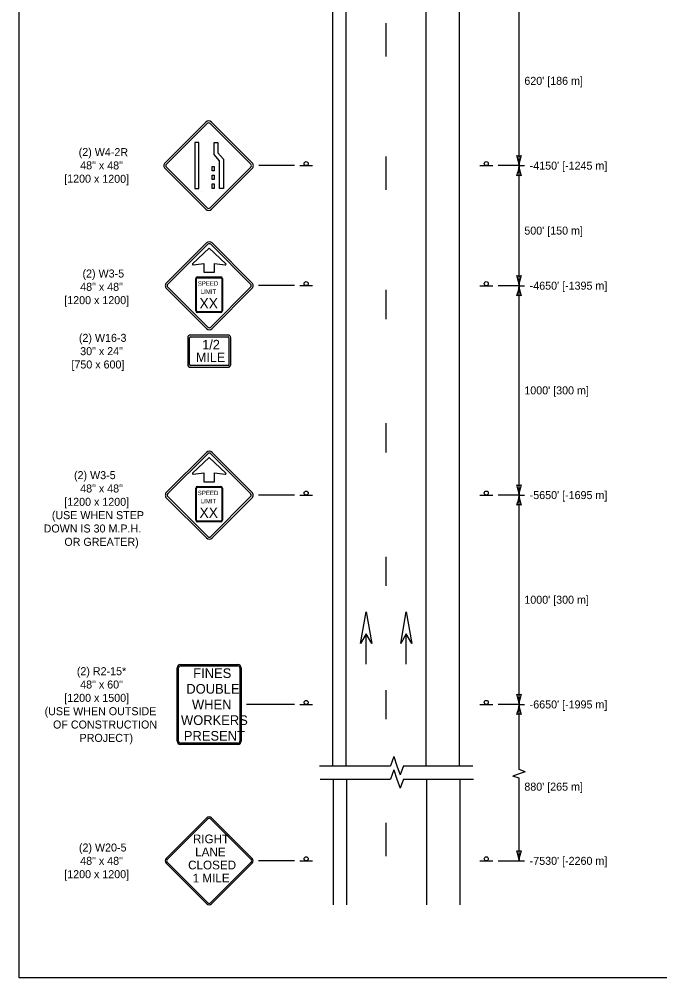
# Model space of a CAD drawing. Extents: x 49991.4 to 50021, y 49987.6 to 50011.4.
# Drawn here: x 49999.38 to 50004.19, y 49987.8 to 49994.99 of the extents above; entities that cross this region are included whole.
import ezdxf

# ---------------------------------------------------------------- set-up
doc = ezdxf.new("R2010")
doc.units = 0
for name, color, linetype in [('Level 1', 7, 'Continuous'), ('Level 2', 7, 'Continuous'), ('Level 25', 7, 'Continuous'), ('Level 3', 7, 'Continuous'), ('Level 6', 7, 'Continuous')]:
    doc.layers.add(name, color=color, linetype=linetype)

msp = doc.modelspace()

# ---------------------------------------------------------------- linework, layer by layer
at = {"layer": 'Level 1'}
for p, q in [((50001.7353, 49989.3888), (50001.7353, 49998.1941)), ((50001.8353, 49989.3888), (50001.8353, 49998.1941)), ((50002.4353, 49989.3888), (50002.4353, 49998.1941)), ((50002.6853, 49989.3888), (50002.6853, 49998.1941)), ((50002.1353, 49994.7064), (50002.1353, 49994.9564)), ((50002.1353, 49993.7064), (50002.1353, 49993.9564)), ((50001.4873, 49993.8881), (50001.5833, 49993.8881)), ((50002.8373, 49993.8882), (50002.9333, 49993.8882)), ((50000.7869, 49993.3085), (50000.4876, 49993.0092)), ((50000.797, 49993.2984), (50000.4977, 49992.9991)), ((50000.8082, 49993.27), (50000.6838, 49993.1527)), ((50000.7869, 49993.3085), (50000.7869, 49993.3085)), ((50000.797, 49993.2984), (50000.797, 49993.2984)), ((50000.9327, 49993.1527), (50000.8082, 49993.27)), ((50001.1188, 49992.9991), (50000.8195, 49993.2984)), ((50001.1289, 49993.0092), (50000.8296, 49993.3085)), ((50000.6879, 49993.1441), (50000.7679, 49993.1541)), ((50000.7679, 49993.1541), (50000.7679, 49993.0886)), ((50000.8486, 49993.0886), (50000.8486, 49993.1541)), ((50000.8486, 49993.1541), (50000.9286, 49993.1441)), ((50000.7204, 49993.0535), (50000.8951, 49993.0535)), ((50000.7204, 49993.0483), (50000.8951, 49993.0483)), ((50000.7679, 49993.0886), (50000.8486, 49993.0886)), ((50000.8077, 49993.0535), (50000.8077, 49993.0535)), ((50000.4977, 49992.9765), (50000.797, 49992.6772)), ((50000.7079, 49992.7997), (50000.7079, 49993.041)), ((50000.7131, 49992.7997), (50000.7131, 49993.041)), ((50000.8195, 49992.6772), (50001.1188, 49992.9765)), ((50000.9024, 49993.041), (50000.9024, 49992.7997)), ((50000.9076, 49993.041), (50000.9076, 49992.7997)), ((50001.4873, 49992.9886), (50001.5833, 49992.9886)), ((50002.8373, 49992.9882), (50002.9333, 49992.9882)), ((50000.4876, 49992.9664), (50000.7869, 49992.6671)), ((50000.8296, 49992.6671), (50001.1289, 49992.9664)), ((50002.1353, 49992.7372), (50002.1353, 49992.9564)), ((50000.8951, 49992.7924), (50000.7204, 49992.7924)), ((50000.8951, 49992.7873), (50000.7204, 49992.7873)), ((50000.9494, 49992.6182), (50000.6671, 49992.6182)), ((50000.647, 49992.5981), (50000.647, 49992.3965)), ((50000.6604, 49992.3965), (50000.6604, 49992.5981)), ((50000.6671, 49992.6048), (50000.9494, 49992.6048)), ((50000.9561, 49992.5981), (50000.9561, 49992.3965)), ((50000.9695, 49992.3965), (50000.9695, 49992.5981)), ((50000.9494, 49992.3898), (50000.6671, 49992.3898)), ((50000.6671, 49992.3763), (50000.9494, 49992.3763)), ((50002.1353, 49991.7372), (50002.1353, 49991.9564)), ((50000.7869, 49991.7384), (50000.4876, 49991.4391)), ((50000.797, 49991.7283), (50000.4977, 49991.429)), ((50000.8082, 49991.6999), (50000.6838, 49991.5826)), ((50000.7869, 49991.7384), (50000.7869, 49991.7384)), ((50000.797, 49991.7283), (50000.797, 49991.7283)), ((50000.9327, 49991.5826), (50000.8082, 49991.6999)), ((50001.1188, 49991.429), (50000.8195, 49991.7283)), ((50001.1289, 49991.4391), (50000.8296, 49991.7384)), ((50000.6879, 49991.574), (50000.7679, 49991.584)), ((50000.7679, 49991.584), (50000.7679, 49991.5185)), ((50000.8486, 49991.5185), (50000.8486, 49991.584)), ((50000.8486, 49991.584), (50000.9286, 49991.574)), ((50000.7079, 49991.2296), (50000.7079, 49991.4709)), ((50000.7131, 49991.2296), (50000.7131, 49991.4709)), ((50000.7204, 49991.4834), (50000.8951, 49991.4834)), ((50000.7204, 49991.4782), (50000.8951, 49991.4782)), ((50000.7679, 49991.5185), (50000.8486, 49991.5185)), ((50000.8077, 49991.4834), (50000.8077, 49991.4834)), ((50000.9024, 49991.4709), (50000.9024, 49991.2296)), ((50000.9076, 49991.4709), (50000.9076, 49991.2296)), ((50000.4876, 49991.3963), (50000.7869, 49991.097)), ((50000.4977, 49991.4064), (50000.797, 49991.1071)), ((50000.8195, 49991.1071), (50001.1188, 49991.4064)), ((50000.8296, 49991.097), (50001.1289, 49991.3963)), ((50001.4873, 49991.4178), (50001.5833, 49991.4178)), ((50002.8373, 49991.4184), (50002.9333, 49991.4184)), ((50000.8951, 49991.2223), (50000.7204, 49991.2223)), ((50000.8951, 49991.2172), (50000.7204, 49991.2172)), ((50002.1353, 49990.7372), (50002.1353, 49990.9564)), ((50001.9853, 49990.1516), (50001.9853, 49990.3776)), ((50001.9856, 49990.1516), (50001.9856, 49990.3776)), ((50002.2853, 49990.1516), (50002.2853, 49990.3776)), ((50002.2856, 49990.1516), (50002.2856, 49990.3776)), ((50000.5682, 49989.5729), (50000.5682, 49990.1229)), ((50000.5782, 49989.5729), (50000.5782, 49990.1229)), ((50000.5932, 49990.1479), (50001.0232, 49990.1479)), ((50000.5932, 49990.1379), (50001.0232, 49990.1379)), ((50001.0382, 49990.1229), (50001.0382, 49989.5729)), ((50001.0482, 49990.1229), (50001.0482, 49989.5729)), ((50002.1353, 49989.7372), (50002.1353, 49989.9564)), ((50001.4873, 49989.8479), (50001.5833, 49989.8479)), ((50002.8373, 49989.8486), (50002.9333, 49989.8486)), ((50001.0232, 49989.5579), (50000.5932, 49989.5579)), ((50001.0232, 49989.5479), (50000.5932, 49989.5479)), ((50001.7405, 49988.3469), (50001.7405, 49989.2888)), ((50001.8405, 49988.3469), (50001.8405, 49989.2888)), ((50002.4405, 49988.3469), (50002.4405, 49989.2888)), ((50002.6905, 49988.3469), (50002.6905, 49989.2888)), ((50000.4865, 49988.6936), (50000.7906, 49988.9976)), ((50000.4936, 49988.6865), (50000.7976, 49988.9906)), ((50000.8189, 49988.9906), (50001.1229, 49988.6865)), ((50000.8259, 49988.9976), (50001.13, 49988.6936)), ((50002.1353, 49988.711), (50002.1353, 49988.961)), ((50000.7976, 49988.3612), (50000.4936, 49988.6653)), ((50001.1229, 49988.6653), (50000.8189, 49988.3612)), ((50001.4873, 49988.6756), (50001.5833, 49988.6756)), ((50002.8373, 49988.6759), (50002.9333, 49988.6759)), ((50000.7906, 49988.3542), (50000.4865, 49988.6582)), ((50001.13, 49988.6582), (50000.8259, 49988.3542))]:
    msp.add_line(p, q, dxfattribs=at)
for points in [[(49999.3835, 49998.9992), (50016.7501, 49998.9992), (50016.7501, 49987.7988), (49999.3835, 49987.7988)], [(50001.9436, 49990.3052), (50001.9853, 49990.5418), (50002.0272, 49990.3052), (50001.9853, 49990.3774)], [(50002.2436, 49990.3052), (50002.2853, 49990.5418), (50002.3272, 49990.3052), (50002.2853, 49990.3774)]]:
    msp.add_lwpolyline(points, close=True, dxfattribs=at)
for centre in [(50001.5353, 49993.9033), (50002.8853, 49993.9034), (50001.5353, 49993.0038), (50002.8853, 49993.0034), (50001.5353, 49991.433), (50002.8853, 49991.4336), (50001.5353, 49989.8631), (50002.8853, 49989.8638), (50001.5353, 49988.6908), (50002.8853, 49988.6912)]:
    msp.add_circle(centre, 0.0152, dxfattribs=at)
for centre, radius, start, end in [((50000.8082, 49993.2871), 0.0302, 45.00007, 134.99993), ((50000.8082, 49993.2871), 0.016, 45.00007, 134.99993), ((50000.6874, 49993.1491), 0.00508, 134.62874, 275.82948), ((50000.9291, 49993.1491), 0.00509, 264.38259, 45.16491), ((50000.7204, 49993.041), 0.0125, 90, 180), ((50000.7204, 49993.041), 0.00728, 90, 180), ((50000.8951, 49993.041), 0.0125, 360, 90), ((50000.8951, 49993.041), 0.00728, 360, 90), ((50000.5089, 49992.9878), 0.0302, 134.99993, 225.00008), ((50000.5089, 49992.9878), 0.016, 134.99993, 225.00008), ((50001.1075, 49992.9878), 0.016, 314.99993, 45.00007), ((50001.1075, 49992.9878), 0.0302, 314.99993, 45.00008), ((50000.7204, 49992.7997), 0.0125, 180, 270), ((50000.7204, 49992.7997), 0.00728, 180, 270), ((50000.8951, 49992.7997), 0.00728, 270, 360), ((50000.8951, 49992.7997), 0.0125, 270, 360), ((50000.6671, 49992.5981), 0.0202, 90, 180), ((50000.8082, 49992.6885), 0.0302, 225.00007, 314.99993), ((50000.8082, 49992.6885), 0.016, 225.00007, 314.99993), ((50000.9494, 49992.5981), 0.0202, 0, 90), ((50000.6671, 49992.5981), 0.00672, 90, 180), ((50000.9494, 49992.5981), 0.00672, 0, 90), ((50000.6671, 49992.3965), 0.0202, 180, 270), ((50000.6671, 49992.3965), 0.00672, 180, 270), ((50000.9494, 49992.3965), 0.00672, 270, 0), ((50000.9494, 49992.3965), 0.0202, 270, 0), ((50000.8082, 49991.717), 0.0302, 45.00007, 134.99993), ((50000.8082, 49991.717), 0.016, 45.00007, 134.99993), ((50000.6874, 49991.579), 0.00508, 134.62874, 275.82948), ((50000.9291, 49991.579), 0.00509, 264.38259, 45.16491), ((50000.7204, 49991.4709), 0.0125, 90, 180), ((50000.7204, 49991.4709), 0.00728, 90, 180), ((50000.8951, 49991.4709), 0.0125, 360, 90), ((50000.8951, 49991.4709), 0.00728, 360, 90), ((50000.5089, 49991.4177), 0.0302, 134.99993, 225.00008), ((50000.5089, 49991.4177), 0.016, 134.99993, 225.00008), ((50001.1075, 49991.4177), 0.016, 314.99993, 45.00007), ((50001.1075, 49991.4177), 0.0302, 314.99993, 45.00008), ((50000.7204, 49991.2296), 0.0125, 180, 270), ((50000.7204, 49991.2296), 0.00728, 180, 270), ((50000.8951, 49991.2296), 0.00728, 270, 360), ((50000.8951, 49991.2296), 0.0125, 270, 360), ((50000.8082, 49991.1184), 0.016, 225.00007, 314.99993), ((50000.8082, 49991.1184), 0.0302, 225.00007, 314.99993), ((50000.5932, 49990.1229), 0.025, 90, 180), ((50000.5932, 49990.1229), 0.015, 90, 180), ((50001.0232, 49990.1229), 0.025, 0, 90), ((50001.0232, 49990.1229), 0.015, 0, 90), ((50000.5932, 49989.5729), 0.025, 180, 270), ((50000.5932, 49989.5729), 0.015, 180, 270), ((50001.0232, 49989.5729), 0.025, 270, 0), ((50001.0232, 49989.5729), 0.015, 270, 0), ((50000.8082, 49988.98), 0.025, 45, 135), ((50000.8082, 49988.98), 0.015, 45, 135), ((50000.5042, 49988.6759), 0.025, 134.99976, 225), ((50000.5042, 49988.6759), 0.015, 134.99976, 225), ((50001.1123, 49988.6759), 0.015, 315, 45), ((50001.1123, 49988.6759), 0.025, 315, 45), ((50000.8082, 49988.3719), 0.025, 225.00043, 315), ((50000.8082, 49988.3719), 0.015, 225.00043, 315)]:
    msp.add_arc(centre, radius, start, end, dxfattribs=at)
at = {"layer": 'Level 2'}
for p, q in [((50000.8448, 49993.9728), (50000.8448, 49994.0617)), ((50000.8448, 49994.0617), (50000.8733, 49994.0617)), ((50000.8733, 49994.0617), (50000.8733, 49993.9834)), ((50000.8733, 49993.9834), (50000.9141, 49993.936)), ((50000.8856, 49993.9255), (50000.8448, 49993.9728)), ((50000.8856, 49993.718), (50000.8856, 49993.9255)), ((50000.9141, 49993.936), (50000.9141, 49993.718)), ((50000.8299, 49993.8485), (50000.8299, 49993.8811)), ((50000.8299, 49993.8811), (50000.845, 49993.8811)), ((50000.845, 49993.8485), (50000.8299, 49993.8485)), ((50000.845, 49993.8811), (50000.845, 49993.8485)), ((50000.8299, 49993.7833), (50000.8299, 49993.8158)), ((50000.8299, 49993.8158), (50000.845, 49993.8158)), ((50000.845, 49993.7833), (50000.8299, 49993.7833)), ((50000.845, 49993.8158), (50000.845, 49993.7833)), ((50000.8296, 49993.718), (50000.8296, 49993.7506)), ((50000.8296, 49993.7506), (50000.8447, 49993.7506)), ((50000.8447, 49993.718), (50000.8296, 49993.718)), ((50000.8447, 49993.7506), (50000.8447, 49993.718)), ((50000.9141, 49993.718), (50000.8856, 49993.718))]:
    msp.add_line(p, q, dxfattribs=at)
at = {"layer": 'Level 25'}
for p, q in [((50000.4772, 49993.9098), (50000.7819, 49994.2145)), ((50000.7922, 49994.2043), (50000.4875, 49993.8996)), ((50000.7922, 49994.2043), (50000.7922, 49994.2043)), ((50001.1199, 49993.8996), (50000.8152, 49994.2043)), ((50000.8255, 49994.2145), (50001.1302, 49993.9098)), ((50000.73, 49994.0617), (50000.7015, 49994.0617)), ((50000.7015, 49994.0617), (50000.7015, 49993.718)), ((50000.73, 49993.718), (50000.73, 49994.0617)), ((50000.7819, 49993.5616), (50000.4772, 49993.8663)), ((50000.4875, 49993.8766), (50000.7922, 49993.5719)), ((50000.8152, 49993.5719), (50001.1199, 49993.8766)), ((50001.1302, 49993.8663), (50000.8255, 49993.5616)), ((50000.7015, 49993.718), (50000.73, 49993.718))]:
    msp.add_line(p, q, dxfattribs=at)
msp.add_lwpolyline([(50000.7487, 49993.6965), (50000.749, 49993.6968)], dxfattribs=at)
for centre, radius, start, end in [((50000.8037, 49994.1928), 0.0308, 45.00007, 134.99993), ((50000.8037, 49994.1928), 0.0162, 45.00007, 134.99993), ((50000.499, 49993.8881), 0.0308, 134.99993, 225.00008), ((50001.1084, 49993.8881), 0.0308, 314.99993, 45.00008), ((50000.499, 49993.8881), 0.0162, 134.99993, 225.00008), ((50001.1084, 49993.8881), 0.0162, 314.99993, 45.00007), ((50000.8037, 49993.5833), 0.0308, 225.00007, 314.99993), ((50000.8037, 49993.5833), 0.0162, 225.00007, 314.99993)]:
    msp.add_arc(centre, radius, start, end, dxfattribs=at)
at = {"layer": 'Level 3'}
for p, q in [((50003.1308, 49989.3603), (50003.1308, 49998.1941)), ((50001.4473, 49993.8881), (50001.1792, 49993.8881)), ((50003.1308, 49993.8882), (50002.9733, 49993.8882)), ((50003.1308, 49993.8882), (50003.1708, 49993.8882)), ((50001.4473, 49992.9886), (50001.1778, 49992.9886)), ((50003.1308, 49992.9882), (50002.9733, 49992.9882)), ((50003.1308, 49992.9882), (50003.1708, 49992.9882)), ((50001.4473, 49991.4178), (50001.1778, 49991.4178)), ((50003.1308, 49991.4184), (50002.9733, 49991.4184)), ((50003.1308, 49991.4184), (50003.1708, 49991.4184)), ((50001.4473, 49989.8479), (50001.0882, 49989.8479)), ((50003.1308, 49989.8486), (50002.9733, 49989.8486)), ((50003.1308, 49989.8486), (50003.1708, 49989.8486)), ((50003.1308, 49989.3279), (50003.0851, 49989.3117)), ((50003.1308, 49989.2955), (50003.0851, 49989.3117)), ((50003.1765, 49989.3441), (50003.1308, 49989.3603)), ((50003.1765, 49989.3441), (50003.1308, 49989.3279)), ((50003.1308, 49988.6759), (50003.1308, 49989.2955)), ((50001.4473, 49988.6759), (50001.1773, 49988.6759)), ((50002.9733, 49988.6759), (50003.1708, 49988.6759))]:
    msp.add_line(p, q, dxfattribs=at)
for centre, radius, start, end in [((50003.1308, 49994.0164), 0.0548, 252.13882, 287.86118), ((50002.8981, 49993.8767), 0.233, 2.82731, 22.07716), ((50003.3529, 49993.879), 0.2223, 157.45601, 177.63952), ((50002.9086, 49993.8974), 0.2223, 337.45601, 357.63952), ((50003.3635, 49993.8997), 0.233, 182.82731, 202.07716), ((50003.1308, 49993.76), 0.0548, 72.13882, 107.86118), ((50003.1308, 49993.1164), 0.0548, 252.13882, 287.86118), ((50002.8981, 49992.9767), 0.233, 2.82731, 22.07716), ((50003.3529, 49992.979), 0.2223, 157.45601, 177.63952), ((50002.9086, 49992.9974), 0.2223, 337.45601, 357.63952), ((50003.3635, 49992.9997), 0.233, 182.82731, 202.07716), ((50003.1308, 49992.86), 0.0548, 72.13882, 107.86118), ((50003.1308, 49991.5466), 0.0548, 252.13882, 287.86118), ((50002.8981, 49991.4069), 0.233, 2.82731, 22.07716), ((50003.3529, 49991.4092), 0.2223, 157.45601, 177.63952), ((50002.9086, 49991.4275), 0.2223, 337.45601, 357.63952), ((50003.3635, 49991.4299), 0.233, 182.82731, 202.07716), ((50003.1308, 49991.2902), 0.0548, 72.13882, 107.86118), ((50003.1308, 49989.9768), 0.0548, 252.13882, 287.86118), ((50002.8981, 49989.8371), 0.233, 2.82731, 22.07716), ((50003.3529, 49989.8394), 0.2223, 157.45601, 177.63952), ((50002.9086, 49989.8577), 0.2223, 337.45601, 357.63952), ((50003.3635, 49989.8601), 0.233, 182.82731, 202.07716), ((50003.1308, 49989.7204), 0.0548, 72.13882, 107.86118), ((50003.1308, 49988.8042), 0.0548, 252.13882, 287.86118), ((50002.8981, 49988.6644), 0.233, 2.82731, 22.07716), ((50003.3529, 49988.6668), 0.2223, 157.45601, 177.63952)]:
    msp.add_arc(centre, radius, start, end, dxfattribs=at)
at = {"layer": 'Level 6'}
for p, q in [((50002.1912, 49989.4574), (50002.1669, 49989.3888)), ((50002.1912, 49989.4574), (50002.2155, 49989.3888)), ((50001.6353, 49989.3888), (50002.1669, 49989.3888)), ((50002.2155, 49989.3888), (50002.2398, 49989.3204)), ((50002.2641, 49989.3888), (50002.2398, 49989.3204)), ((50002.2641, 49989.3888), (50002.7853, 49989.3888)), ((50002.1912, 49989.3574), (50002.1669, 49989.2888)), ((50002.1912, 49989.3574), (50002.2155, 49989.2888)), ((50001.6405, 49989.2888), (50002.1669, 49989.2888)), ((50002.2155, 49989.2888), (50002.2398, 49989.2204)), ((50002.2641, 49989.2888), (50002.2398, 49989.2204)), ((50002.2641, 49989.2888), (50002.7905, 49989.2888))]:
    msp.add_line(p, q, dxfattribs=at)

# ---------------------------------------------------------------- texts
at = {"layer": 'Level 1'}
for s, height, p in [('SPEED', 0.03301, (50000.7224, 49992.9878)), ('LIMIT', 0.03301, (50000.7443, 49992.9268)), ('XX', 0.07775, (50000.7352, 49992.8174)), ('SPEED', 0.03301, (50000.7224, 49991.4177)), ('XX', 0.07775, (50000.7352, 49991.2473)), ('LIMIT', 0.03301, (50000.7443, 49991.3567))]:
    msp.add_text(s, height=height, rotation=360, dxfattribs=at).set_placement(p)
for s, height, p in [('1/2', 0.07124, (50000.7559, 49992.5107)), ('MILE', 0.06989, (50000.7095, 49992.4166)), ('FINES', 0.0725, (50000.6884, 49990.0469)), ('DOUBLE', 0.0725, (50000.6368, 49989.9294)), ('WHEN', 0.0725, (50000.6789, 49989.8119)), ('WORKERS', 0.0725, (50000.5966, 49989.6944)), ('PRESENT', 0.0725, (50000.6181, 49989.5769)), ('RIGHT', 0.06543, (50000.6859, 49988.8077)), ('LANE', 0.06543, (50000.7029, 49988.7097)), ('CLOSED', 0.06543, (50000.6499, 49988.6118)), ('1 MILE', 0.06543, (50000.684, 49988.5139))]:
    msp.add_text(s, height=height, dxfattribs=at).set_placement(p)
at = {"layer": 'Level 2'}
for s, height, p in [("620' [186 m]", 0.06, (50003.1708, 49994.4941)), ("-4150' [-1245 m]", 0.06, (50003.2108, 49993.8582)), ("500' [150 m]", 0.06, (50003.1708, 49993.3711)), ('(2) W3-5', 0.05999, (49999.8583, 49993.0495)), ('48" x 48"', 0.05999, (49999.841, 49992.9496)), ("-4650' [-1395 m]", 0.06, (50003.2108, 49992.9582)), ('[1200 x 1200]', 0.059993, (49999.7216, 49992.8497)), ('(2) W16-3', 0.05999, (49999.8311, 49992.5672)), ('30" x 24"', 0.05999, (49999.841, 49992.4673)), ('[750 x 600]', 0.059993, (49999.7754, 49992.3674)), ("1000' [300 m]", 0.06, (50003.1708, 49992.1733)), ('(2) W3-5', 0.06, (49999.7947, 49991.5377)), ('48" x 48"', 0.06, (49999.841, 49991.4377)), ('[1200 x 1200]', 0.06, (49999.7215, 49991.3377)), ("-5650' [-1695 m]", 0.06, (50003.2108, 49991.3882)), ('(USE WHEN STEP', 0.06, (49999.6282, 49991.2377)), ('DOWN IS 30 M.P.H.', 0.06, (49999.567, 49991.1377)), ('OR GREATER)', 0.06, (49999.7224, 49991.0377)), ("1000' [300 m]", 0.06, (50003.1708, 49990.6035)), ('(2) R2-15*', 0.06, (49999.8158, 49990.0679)), ('48" x 60"', 0.06, (49999.841, 49989.9679)), ('[1200 x 1500]', 0.06, (49999.7215, 49989.8679)), ('(USE WHEN OUTSIDE', 0.06, (49999.574, 49989.7679)), ("-6650' [-1995 m]", 0.06, (50003.2108, 49989.8186)), ('OF CONSTRUCTION', 0.06, (49999.6374, 49989.6679)), ('PROJECT)', 0.06, (49999.8362, 49989.5679)), ("880' [265 m]", 0.06, (50003.1708, 49989.2021)), ('(2) W20-5', 0.06, (49999.8314, 49988.7459)), ('48" x 48"', 0.06, (49999.841, 49988.6459)), ("-7530' [-2260 m] ", 0.06, (50003.2108, 49988.6459)), ('[1200 x 1200]', 0.06, (49999.7215, 49988.5459))]:
    msp.add_text(s, height=height, dxfattribs=at).set_placement(p)
for s, p in [('(2) W4-2R', (49999.8297, 49993.9607)), ('48" x 48"', (49999.8409, 49993.8606)), ('[1200 x 1200]', (49999.721, 49993.7611))]:
    msp.add_text(s, height=0.06, rotation=359.76569, dxfattribs=at).set_placement(p)

doc.saveas('drawing.dxf')
